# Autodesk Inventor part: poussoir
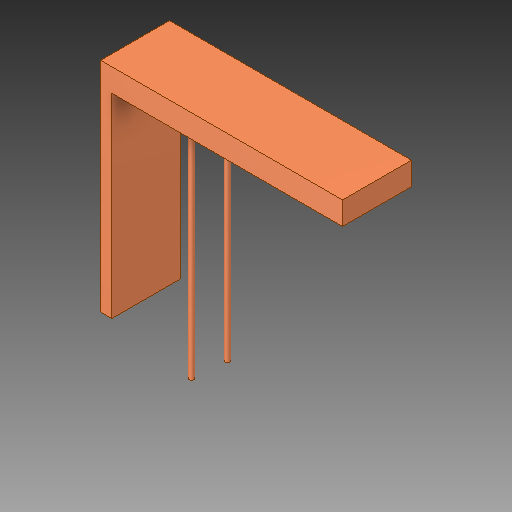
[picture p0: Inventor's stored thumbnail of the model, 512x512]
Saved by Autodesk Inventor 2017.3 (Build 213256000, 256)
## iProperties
Created: 2011-01
Part Number: poussoir
Material: Générique
Document SubType Name: Modeling
Designer: ficho
Density: 1 g/cm^3
Appearance: Par défaut
Author: ficho
Sending System: SolidWorks 2009
Last Author: christophe
Last Saved: 2011-01-23
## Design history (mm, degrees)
extrude "Extrusion2"
node "Solide1"
